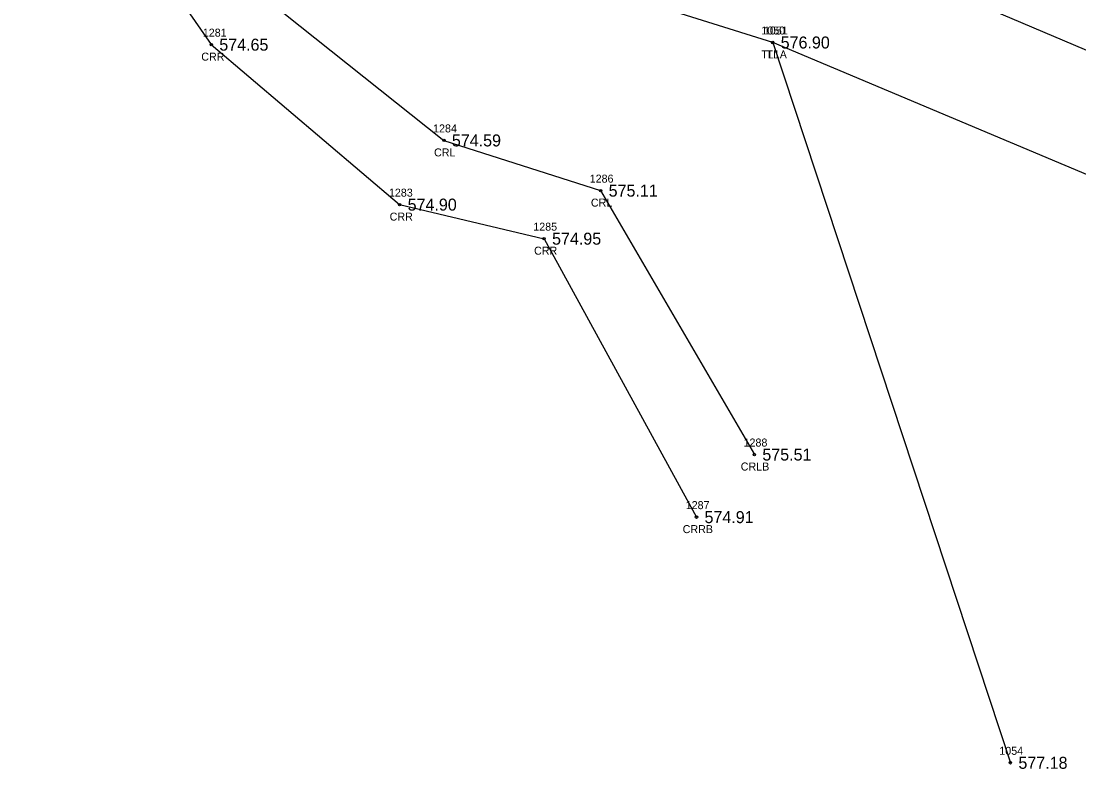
# Model space of a CAD drawing. Extents: x 1664393 to 1667175, y 987029 to 988607.
# Drawn here: x 1665633.2 to 1665765.4, y 987555.5 to 987649.2 of the extents above; entities that cross this region are included whole.
import ezdxf

# ---------------------------------------------------------------- set-up
doc = ezdxf.new("R2010")
doc.units = 0
for name, color, linetype in [('RD_EX_H2O', 7, 'Continuous'), ('RD_EX_H2O_txCode', 7, 'Continuous'), ('RD_EX_Road', 7, 'Continuous'), ('RD_EX_TX_H2O_ELEV', 7, 'Continuous'), ('RD_EX_TX_VEG_ELEV', 7, 'Continuous'), ('RD_EX_VEG', 7, 'Continuous'), ('RD_EX_VEG_txCode', 7, 'Continuous'), ('RD_SMD_Locator', 7, 'Continuous')]:
    doc.layers.add(name, color=color, linetype=linetype)

msp = doc.modelspace()

# ---------------------------------------------------------------- linework, layer by layer
at = {"layer": 'RD_EX_H2O'}
for points in [[(1665565.69, 987792.78), (1665555.48, 987787.59), (1665542.58, 987772.17), (1665532.86, 987767.81), (1665532.86, 987767.81), (1665523.69, 987745.83), (1665522.12, 987740.87), (1665518.2, 987735.79), (1665482.82, 987708), (1665483.87, 987700.87), (1665513.49, 987706.09), (1665528.04, 987685.52), (1665561.97, 987665.98), (1665593.48, 987679.22), (1665619.37, 987685.12), (1665642.78, 987680.31), (1665663.97, 987651.85), (1665686.03, 987634.26), (1665705.62, 987627.98), (1665724.83, 987594.97)], [(1665567.27, 987659), (1665585.72, 987665.81), (1665597.03, 987673.28), (1665619.21, 987679.02), (1665636.86, 987675.2), (1665656.96, 987646.24), (1665680.5, 987626.23), (1665698.55, 987621.97), (1665717.6, 987587.14)]]:
    msp.add_lwpolyline(points, dxfattribs=at)
at = {"layer": 'RD_EX_Road'}
msp.add_lwpolyline([(1666156.67, 987480.61), (1666109.28, 987500.74), (1666063.55, 987520.04), (1666017.04, 987539.82), (1665971.11, 987559.14), (1665924.88, 987578.79), (1665879.5, 987597.89), (1665833.22, 987617.38), (1665786.91, 987636.81), (1665741.44, 987656.13), (1665695.81, 987675.2), (1665649.26, 987694.85), (1665603.56, 987714.71), (1665558.4, 987733.87), (1665524.71, 987748.93)], dxfattribs=at)
at = {"layer": 'RD_EX_VEG'}
msp.add_line((1665727.12, 987646.51), (1665756.83, 987556.41), dxfattribs=at)
msp.add_lwpolyline([(1666150.2, 987465.22), (1665963.16, 987547.12), (1665727.12, 987646.51), (1665543.18, 987704.13), (1665449.91, 987737.53), (1665163.85, 987870.35), (1665156.07, 987854.03)], dxfattribs=at)
at = {"layer": 'RD_SMD_Locator'}
for centre in [(1665656.96, 987646.24), (1665727.12, 987646.51), (1665727.12, 987646.51), (1665686.03, 987634.26), (1665705.62, 987627.98), (1665680.5, 987626.23), (1665698.55, 987621.97), (1665724.83, 987594.97), (1665717.6, 987587.14), (1665756.83, 987556.41)]:
    msp.add_circle(centre, 0.15, dxfattribs=at)

# ---------------------------------------------------------------- texts
at = {"layer": 'RD_EX_H2O_txCode'}
for s, p in [('1281', (1665655.9, 987647.24)), ('CRR', (1665655.71, 987644.24)), ('1284', (1665684.68, 987635.26)), ('CRL', (1665684.8, 987632.26)), ('1286', (1665704.25, 987628.98)), ('1283', (1665679.16, 987627.23)), ('CRL', (1665704.4, 987625.98)), ('CRR', (1665679.25, 987624.23)), ('1285', (1665697.2, 987622.97)), ('CRR', (1665697.3, 987619.97)), ('1288', (1665723.48, 987595.97)), ('CRLB', (1665723.13, 987592.97)), ('1287', (1665716.25, 987588.14)), ('CRRB', (1665715.87, 987585.14))]:
    msp.add_text(s, height=1, dxfattribs=at).set_placement(p)
at = {"layer": 'RD_EX_TX_H2O_ELEV'}
for s, p in [('574.65', (1665657.96, 987645.49)), ('574.59', (1665687.03, 987633.51)), ('575.11', (1665706.62, 987627.23)), ('574.90', (1665681.5, 987625.48)), ('574.95', (1665699.55, 987621.22)), ('575.51', (1665725.83, 987594.22)), ('574.91', (1665718.6, 987586.39))]:
    msp.add_text(s, height=1.5, dxfattribs=at).set_placement(p)
at = {"layer": 'RD_EX_TX_VEG_ELEV'}
for s, p in [('576.90', (1665728.12, 987645.76)), ('576.90', (1665728.12, 987645.76)), ('577.18', (1665757.83, 987555.66))]:
    msp.add_text(s, height=1.5, dxfattribs=at).set_placement(p)
at = {"layer": 'RD_EX_VEG_txCode'}
for s, p in [('1050', (1665725.7, 987647.51)), ('1051', (1665726.02, 987647.51)), ('TL1A', (1665725.7, 987644.51)), ('TL', (1665726.35, 987644.51)), ('1054', (1665755.44, 987557.41))]:
    msp.add_text(s, height=1, dxfattribs=at).set_placement(p)

doc.saveas('drawing.dxf')
